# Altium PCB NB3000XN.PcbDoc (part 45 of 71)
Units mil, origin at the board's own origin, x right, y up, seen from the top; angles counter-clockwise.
Board outline 9527.56 x 6929.77 mil, 6 copper layers (Top Layer, GND+SHIELD, MidLayer1, MidLayer2, P2 - 3V3+5V0, Bottom Layer), stack 62.375 mil thick; 832 components, 1027 nets, 4655 pads, 4981 vias.
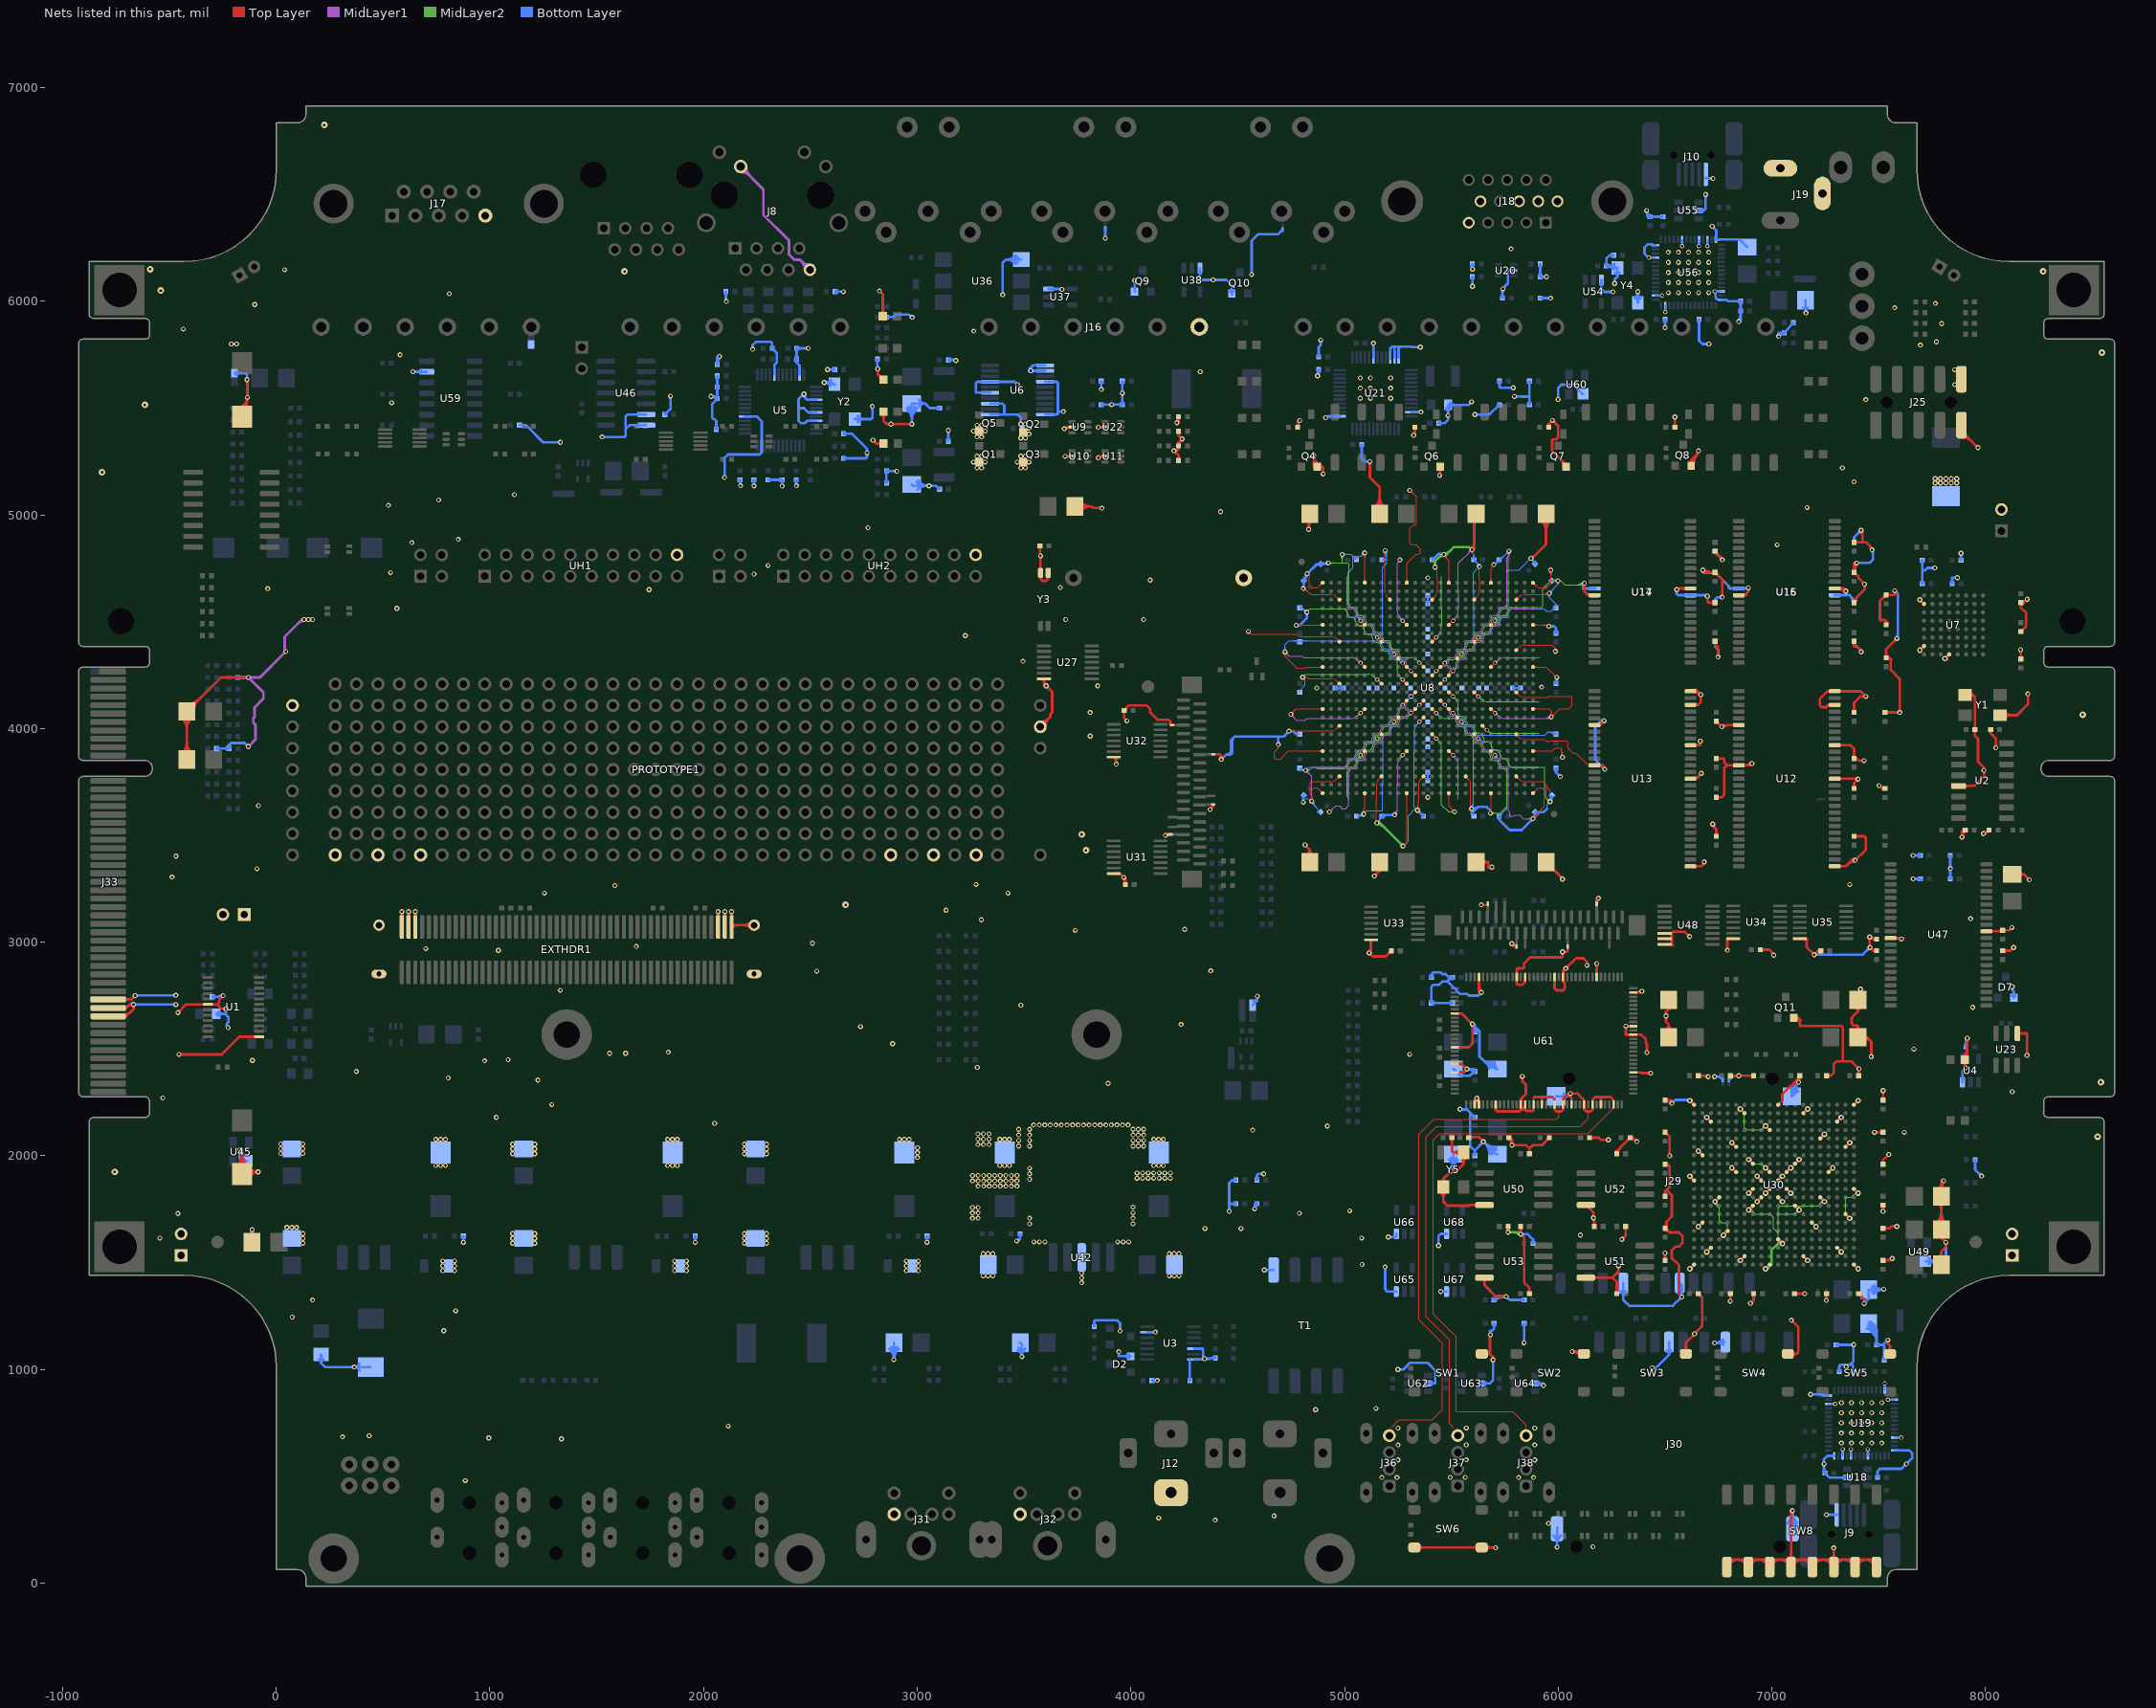
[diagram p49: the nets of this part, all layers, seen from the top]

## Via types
v1: diameter 23, hole 11.81, Top Layer to Bottom Layer, 3672 vias
v2: diameter 26, hole 11.81, Top Layer to Bottom Layer, 461 vias
v3: diameter 19, hole 11.81, Top Layer to Bottom Layer, tented both sides, 396 vias
v4: diameter 23.62, hole 11.81, Top Layer to Bottom Layer, 288 vias
v5: diameter 20, hole 11.81, Top Layer to Bottom Layer, 91 vias
v6: diameter 23, hole 11.81, Top Layer to Bottom Layer, tented both sides, 50 vias
v7: diameter 31, hole 11.81, Top Layer to Bottom Layer, 15 vias
v8: diameter 27.56, hole 11.81, Top Layer to Bottom Layer, tented both sides, 4 vias
v9: diameter 29, hole 11.81, Top Layer to Bottom Layer, 3 vias
v10: diameter 21, hole 11.81, Top Layer to Bottom Layer, 1 vias

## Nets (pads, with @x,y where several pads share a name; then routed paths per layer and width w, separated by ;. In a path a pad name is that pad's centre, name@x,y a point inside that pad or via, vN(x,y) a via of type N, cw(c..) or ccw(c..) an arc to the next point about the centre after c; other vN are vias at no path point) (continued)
GND: (continued)
  Bottom Layer w12: J33.B38@-785.98,2731.6 -678.25,2731.6 v1(-659.81,2750.04) -658.04,2751.81 v1(-470,2751.81) ; J33.B38@-711.58,2726.1 cw(c-698.3,2712.82) -698.3,2731.6 cw(c-698.3,2750.38) J33.B38@-711.58,2737.1 ; v1(-668.14,2708.37) -667.96,2708.19 v1(-470,2708.19) ; v1@-665.31,2750.04 cw(c-678.59,2750.04) -669.2,2740.65 cw(c-659.81,2731.26) v1@-659.81,2744.54 ; v1@-664.25,2704.49 cw(c-655.31,2695.55) -655.31,2708.19 ; v1@-664.25,2712.26 ccw(c-654.42,2722.1) -654.42,2708.19 ; v1@-655.92,2746.15 cw(c-642.26,2732.49) -642.26,2751.81 ; v1@-473.89,2704.3 ccw(c-483.28,2694.91) -483.28,2708.19 ccw(c-483.28,2721.47) v1@-473.89,2712.08 ; v1@-473.89,2747.92 ccw(c-483.28,2738.53) -483.28,2751.81 ccw(c-483.28,2765.09) v1@-473.89,2755.7 ; C21.2@-299.33,2745 -263.81,2745 -259.81,2749 -258.81,2750.04 v1(-248.48,2750.04) ; C21.2@-295.22,2740.89 cw(c-285.3,2730.97) -285.3,2745 ; C21.2@-295.22,2749.11 ccw(c-285.3,2759.03) -285.3,2745 ; C20.2@-280.63,2665 -239.81,2665 ; C13.2@-279.33,3906.82 C7.2@-220.67,3906.82 -220.67,3924.33 -212.63,3932.37 ; C13.2@-275.22,3902.71 cw(c-265.3,3892.79) -265.3,3906.82 ; C13.2@-275.22,3910.93 ccw(c-265.3,3920.85) -265.3,3906.82 ; -273.92,2745 ccw(c-273.92,2775.49) v1@-252.36,2753.93 ; C20.2@-270.95,2655.32 cw(c-247.59,2631.96) -247.59,2665 cw(c-247.59,2698.04) C20.2@-270.95,2674.68 ; v1@-238.36,2684.49 cw(c-247.75,2675.1) -234.48,2675.1 cw(c-221.2,2675.1) v1@-230.59,2684.49 ; v1(-234.48,2688.37) -234.48,2670.33 -239.81,2665 ; C7.2@-226.03,3903.73 cw(c-213.41,3910.99) -223.71,3921.29 ; v1(-225,2600) -233,2608 -233,2616.59 ; C7.2@-224.78,3902.71 ccw(c-234.7,3892.79) -234.7,3906.82 ccw(c-234.7,3920.85) -224.78,3910.93 ccw(c-234.7,3920.85) -220.67,3920.85 ccw(c-206.64,3920.85) C7.2@-216.56,3910.93 ; v1@-223.88,2605.38 cw(c-221.55,2616.59) -233,2616.59 ; C7.2@-215.63,3909.71 cw(c-199.33,3919.08) -212.63,3932.37 ; NT1.2@-194.76,5662.8 -142.79,5662.79 -136.48,5656.48 v1(-136.48,5633.37) -134.81,5631.71 v1(-134.81,5550.04) ; NT1.2@-187.87,5655.9 cw(c-171.23,5639.26) -171.23,5662.79 cw(c-171.23,5686.33) NT1.2@-187.87,5669.69 ; C18.2@-179.33,4239.55 -130.65,4239.54 v1(-130.48,4239.37) ; C18.2@-175.22,4235.44 cw(c-165.3,4225.52) -165.3,4239.54 ; C18.2@-175.22,4243.65 ccw(c-165.3,4253.57) -165.3,4239.54 ; v1(-171.14,2028.04) -171.14,1986.14 -161.69,1976.69 U45.1@-135.93,1976.69 ; -144.16,4239.54 cw(c-144.16,4225.69) v1@-134.36,4235.49 ; -143.34,4239.54 ccw(c-143.34,4252.24) v1@-134.36,4243.26 ; v1@-140.36,5629.49 cw(c-153.78,5616.07) -134.81,5616.07 ; v1@-140.36,5637.26 ccw(c-149.75,5646.65) -136.48,5646.65 ccw(c-123.2,5646.65) v1@-132.59,5637.26 ; v1@-138.7,5553.93 ccw(c-148.09,5563.32) -134.81,5563.32 ccw(c-121.53,5563.32) v1@-130.92,5553.93 ; v1@-135.98,3915.37 ccw(c-149.25,3915.37) -139.86,3924.76 ccw(c-130.48,3934.15) v1@-130.48,3920.87 ; v1(-130.48,3915.37) -147.48,3932.37 -212.63,3932.37 ; R111.2@199.3,1046.74 cw(c191.56,1030) 210,1030 ; R111.2@210,1069.88 210,1030 ; R111.2@220.7,1046.74 ccw(c228.44,1030) 210,1030 ; v1@361.3,1007.82 ccw(c351.91,998.43) 351.91,1011.71 ccw(c351.91,1024.99) v1@361.3,1015.6 ; v1@369.08,1007.82 cw(c378.72,998.18) 378.72,1011.81 ; v1@369.08,1015.6 ccw(c378.22,1024.74) 378.22,1011.81 ; C87.2@390.77,995.28 ccw(c365.19,983.76) v1@365.19,1011.81 ; C87.2@390.77,1028.34 cw(c365.19,1039.86) v1@365.19,1011.81 ; C87.2@439.24,1011.81 v1@365.19,1011.81 ; v4(639.92,5670.08) U59.15@704.59,5670.08 ; v4@644.03,5665.97 cw(c653.95,5656.05) 653.95,5670.08 cw(c653.95,5684.11) v4@644.03,5674.19 ; U59.15@677.44,5664.58 ccw(c664.16,5651.3) 664.16,5670.08 ccw(c664.16,5688.86) U59.15@677.44,5675.58 ; v1@872.29,1599.08 ccw(c862.9,1608.47) 876.18,1608.47 ccw(c889.46,1608.47) v1@880.07,1599.08 ; R206.2@872.42,1620.75 cw(c863.34,1611.67) 876.18,1611.67 cw(c889.02,1611.67) R206.2@879.94,1620.75 ; v1(876.18,1595.19) R206.2@876.18,1625 ; C151.2@1137.78,5420.08 1169.92,5420.08 1250,5340 v1(1330,5340) ; v1@1326.11,5336.11 ccw(c1316.72,5326.72) 1316.72,5340 ccw(c1316.72,5353.28) v1@1326.11,5343.89 ; v1(1525,5365) 1630,5365 1635,5370 1635,5401.16 ; v1@1528.89,5361.11 cw(c1538.28,5351.72) 1538.28,5365 cw(c1538.28,5378.28) v1@1528.89,5368.89 ; U46.7@1695.94,5415.97 ccw(c1686.02,5406.05) 1686.02,5420.08 ccw(c1686.02,5434.11) U46.7@1695.94,5424.19 ; U46.6@1695.94,5465.97 ccw(c1686.02,5456.05) 1686.02,5470.08 ccw(c1686.02,5484.11) U46.6@1695.94,5474.19 ; U46.7@1731.54,5420.08 1653.92,5420.08 1635,5401.16 ; U46.6@1731.54,5470.08 1645.08,5470.08 1635,5460 1635,5401.16 ; C152.1@1819.33,5470 1845.19,5495.86 v1(1845.19,5556.71) ; C152.1@1819.33,5475.81 ccw(c1819.33,5489.84) 1829.25,5479.92 ccw(c1839.17,5470) C152.1@1825.14,5470 ; v1@1841.3,5552.82 cw(c1831.91,5543.43) 1845.19,5543.43 cw(c1858.47,5543.43) v1@1849.08,5552.82 ; v1@1957.29,1598.89 ccw(c1947.9,1608.28) 1961.18,1608.28 ccw(c1974.46,1608.28) v1@1965.07,1598.89 ; R204.2@1957.42,1620.75 cw(c1948.34,1611.67) 1961.18,1611.67 cw(c1974.02,1611.67) R204.2@1964.94,1620.75 ; v1(1961.18,1595) R204.2@1961.18,1625 ; v1@2038.89,5551.11 cw(c2048.28,5541.72) 2048.28,5555 cw(c2048.28,5568.28) v1@2038.89,5558.89 ; 2052.94,5531.08 ccw(c2039.51,5544.51) R52.2@2058.5,5544.51 ; C50.1@2055.22,5404.11 ccw(c2045.3,5414.03) 2059.33,5414.03 ccw(c2073.36,5414.03) C50.1@2063.44,5404.11 ; C50.1@2059.33,5400 2059.33,5440.37 2052,5447.71 2048.52,5447.71 2040.19,5456.04 2040.19,5518.33 2063.82,5541.96 R52.2@2063.82,5545 ; R52.2@2059.49,5542.4 ccw(c2035,5524.9) v1(2035,5555) 2053.82,5555 R52.2@2063.82,5545 ; R52.2@2060.06,5549.25 ccw(c2050.98,5558.33) 2063.82,5558.33 ccw(c2076.66,5558.33) R52.2@2067.58,5549.25 ; R51.2@2060.06,5594.08 cw(c2050.98,5585) 2063.82,5585 ; R51.2@2060.06,5602.59 ccw(c2050.98,5611.67) 2063.82,5611.67 ccw(c2076.66,5611.67) R51.2@2067.58,5602.59 ; R47.2@2060.06,5647.41 cw(c2050.98,5638.33) 2063.82,5638.33 cw(c2076.66,5638.33) R47.2@2067.58,5647.41 ; R46.2@2060.06,5709.25 ccw(c2050.98,5718.33) 2063.82,5718.33 ccw(c2076.66,5718.33) R46.2@2067.58,5709.25 ; 2063.82,5585 cw(c2076.66,5585) R51.2@2067.58,5594.08 ; R47.2@2063.82,5651.67 R51.2@2063.82,5598.33 R52.2@2063.82,5545 ; R46.2@2063.82,5703.47 cw(c2111.53,5703.47) v1@2078.35,5737.76 ; R46.2@2063.82,5705 2063.82,5731.04 2066.15,5733.37 ; 2063.82,5731.79 cw(c2084.13,5731.79) v1@2070,5746.38 ; v1(2074.52,5741.71) 2066.15,5733.37 ; v1(2074.52,5741.71) 2066.19,5733.37 ; v1@2094.64,5179.08 ccw(c2085.25,5188.47) 2098.52,5188.47 ccw(c2111.8,5188.47) v1@2102.41,5179.08 ; v1(2098.52,5175.19) 2098.52,5266.37 2115.19,5283.04 2263.62,5283.04 2272.28,5291.71 U5.11@2272.28,5322.68 2272.28,5437.72 2252.85,5457.15 ; C43.2@2100.22,6040.89 cw(c2090.3,6030.97) 2104.33,6030.97 cw(c2118.36,6030.97) C43.2@2108.44,6040.89 ; 2104.33,6018.42 ccw(c2126.23,6018.42) v1@2110.75,6002.93 ; C43.2@2104.33,6045 2104.33,6001.57 v1(2106.86,5999.04) ; R45.2@2166.24,5160.06 cw(c2157.16,5150.98) 2170,5150.98 cw(c2182.84,5150.98) R45.2@2173.76,5160.06 ; R45.2@2170,5157.69 ccw(c2194.17,5157.69) v1@2177.08,5140.6 ; R45.2@2170,5163.82 2170,5139.71 2170.19,5139.71 v1(2173.19,5136.71) ; U5.17@2193.54,5460.47 2249.53,5460.47 2252.85,5457.15 ; v1@2226.11,5778.89 ccw(c2216.72,5788.28) 2230,5788.28 ccw(c2243.28,5788.28) v1@2233.89,5778.89 ; v1(2230,5775) 2230,5795 2245,5810 2315,5810 2321.18,5803.82 R56.1@2321.18,5780 2342.5,5758.68 2342.5,5712.35 2331.34,5701.19 U5.29@2331.34,5657.32 ; v1@2231.97,5140.26 ccw(c2222.23,5150) 2236,5150 ; R44.2@2232.24,5160.06 cw(c2223.16,5150.98) 2236,5150.98 cw(c2248.84,5150.98) R44.2@2239.76,5160.06 ; v1@2235.71,5136.52 2235.86,5136.52 v1@2236,5136.52 ; 2236,5149.31 ccw(c2248.79,5149.31) v1@2239.75,5140.26 ; R44.2@2236,5163.82 v1@2236,5136.52 ; v1@2236.67,5135.56 v1(2235.86,5136.37) v1@2236,5136.52 ; 2255,5455 2252.85,5457.15 ; 2267.34,5286.76 ccw(c2255.38,5298.72) U5.11@2272.28,5299.15 ; R43.2@2302,5163.82 R42.2@2368,5163.82 v1(2368,5135) ; R43.2@2306.25,5160.06 cw(c2315.33,5150.98) 2315.33,5163.82 cw(c2315.33,5176.66) R43.2@2306.25,5167.58 ; R56.1@2317.42,5784.25 ccw(c2308.34,5793.33) 2321.18,5793.33 ccw(c2334.02,5793.33) R56.1@2324.94,5784.25 ; R56.1@2321.18,5774.19 cw(c2321.18,5760.16) R56.1@2331.1,5770.08 ; R56.1@2326.5,5779.51 ccw(c2338.15,5779.51) R56.1@2329.91,5771.27 ; R42.2@2363.75,5160.06 ccw(c2354.67,5150.98) 2354.67,5163.82 ccw(c2354.67,5176.66) R42.2@2363.75,5167.58 ; v1@2364.11,5138.89 ccw(c2354.72,5148.28) 2368,5148.28 ccw(c2381.28,5148.28) v1@2371.89,5138.89 ; R42.2@2364.24,5160.06 cw(c2355.16,5150.98) 2368,5150.98 cw(c2380.84,5150.98) R42.2@2371.76,5160.06 ; R41.2@2430.24,5160.06 cw(c2421.16,5150.98) 2434,5150.98 cw(c2446.84,5150.98) R41.2@2437.76,5160.06 ; R41.2@2430.73,5160.06 cw(c2420.42,5149.75) 2435,5149.75 ; C44.2@2430.8,5733.82 ccw(c2440.39,5726.3) 2431.77,5717.68 ; v1@2431.3,5140.6 ccw(c2422.37,5149.53) 2435,5149.53 ; C44.2@2431.56,5734.11 ccw(c2421.64,5744.03) 2435.67,5744.03 ccw(c2449.7,5744.03) C44.2@2439.78,5734.11 ; C47.1@2431.56,5775.89 cw(c2421.64,5765.97) 2435.67,5765.97 cw(c2449.7,5765.97) 2439.78,5775.89 cw(c2449.7,5765.97) 2449.7,5780 ; R41.2@2434,5152.86 ccw(c2451.34,5152.86) 2439.08,5140.6 cw(c2448.93,5150.44) 2435,5150.44 ; 2435,5152.2 cw(c2446.11,5152.2) R41.2@2438.25,5160.06 ; C47.1@2439.78,5784.11 ccw(c2449.7,5794.03) 2449.7,5780 ; C44.2@2440.24,5726.41 ccw(c2451.11,5717.88) 2441.34,5708.11 ; 2445,5485 2445,5455 ; U5.35@2449.45,5657.32 2449.45,5700 2435.67,5713.78 C44.2@2435.67,5730 C47.1@2435.67,5775.04 ; v4@2464.19,5566.71 cw(c2450.16,5566.71) 2460.08,5556.79 cw(c2470,5546.87) v4@2470,5560.9 ; v4@2475.21,5564.14 ccw(c2489.68,5557.02) 2478.28,5545.62 ; v1@2484.23,5780 C47.1@2440.63,5780 ; v1@2486.11,5776.11 ccw(c2476.72,5766.72) 2476.72,5780 ccw(c2476.72,5793.28) v1@2486.11,5783.89 ; U5.45@2528.19,5440.79 2485.79,5440.79 2475,5430 2455,5430 2445,5440 2445,5455 ; U5.43@2528.19,5480.16 2489.84,5480.16 2470,5500 2445,5500 ; U5.40@2528.19,5539.21 2484.68,5539.21 2470,5553.9 v4(2470,5566.71) 2445,5541.71 2445,5500 ; v4@2569.11,5615.89 cw(c2579.03,5605.97) 2579.03,5620 cw(c2579.03,5634.03) v4@2569.11,5624.11 ; v4@2571.46,5620 ccw(c2571.46,5656.54) Y2.4@2597.3,5630.7 ; v4(2580,5680) C45.1@2614.33,5680 C45.1@2612.5,5680 ; v4@2584.11,5675.89 cw(c2594.03,5665.97) 2594.03,5680 cw(c2594.03,5694.03) v4@2584.11,5684.11 ; Y2.4@2594.39,5603.91 ccw(c2565,5585.11) v4(2565,5620) 2596.5,5620 2605,5611.5 Y2.4@2612.5,5611.5 ; C45.1@2610.22,5675.89 ccw(c2600.3,5665.97) 2600.3,5680 ccw(c2600.3,5694.03) C45.1@2610.22,5684.11 ; C48.1@2615.67,6045 v1(2655,6045) ; C48.1@2619.78,6040.89 cw(c2629.7,6030.97) 2629.7,6045 cw(c2629.7,6059.03) C48.1@2619.78,6049.11 ; C51.1@2655.67,5265 2760,5265 2765,5270 v1(2765,5290) 2765,5310 2695,5380 C46.1@2655.67,5380 ; C51.1@2659.78,5260.89 cw(c2669.7,5250.97) 2669.7,5265 cw(c2669.7,5279.03) C51.1@2659.78,5269.11 ; C46.1@2659.78,5375.89 cw(c2669.7,5365.97) 2669.7,5380 cw(c2669.7,5394.03) C46.1@2659.78,5384.11 ; Y2.2@2707.5,5448.5 2783.5,5448.5 2790.19,5455.19 v1(2790.19,5508.37) ; Y2.2@2722.7,5433.3 cw(c2759.41,5396.59) 2759.41,5448.5 cw(c2759.41,5500.41) Y2.2@2722.7,5463.7 ; v1@2761.11,5286.11 cw(c2751.72,5276.72) 2765,5276.72 cw(c2778.28,5276.72) v1@2768.89,5286.11 ; v1@2761.11,5293.89 ccw(c2751.72,5303.28) 2765,5303.28 ccw(c2778.28,5303.28) v1@2768.89,5293.89 ; v1@2786.3,5504.49 cw(c2776.91,5495.1) 2790.19,5495.1 cw(c2803.47,5495.1) v1@2794.08,5504.49 ; R64.1@2810.06,5725.75 cw(c2800.98,5716.67) 2813.82,5716.67 cw(c2826.66,5716.67) R64.1@2817.58,5725.75 ; 2813.82,5699.96 ccw(c2831.78,5699.96) v1@2819.08,5687.26 ; R64.1@2813.82,5730 2813.82,5684.75 v1(2815.19,5683.37) ; R61.2@2852.42,5154.25 ccw(c2843.34,5163.33) 2856.18,5163.33 ccw(c2869.02,5163.33) R61.2@2859.94,5154.25 ; R65.2@2852.42,5200.75 cw(c2843.34,5191.67) 2856.18,5191.67 cw(c2869.02,5191.67) R65.2@2859.94,5200.75 ; R61.2@2856.18,5150 R65.2@2856.18,5205 2904.23,5205 v1(2904.52,5204.71) ; R60.1@2856.18,5926 2887.63,5926 2900,5938.37 2915.19,5938.37 2960.19,5938.37 2973.52,5925.04 v1(2976.52,5925.04) ; R65.2@2859.94,5201.24 cw(c2869.02,5192.16) 2869.02,5205 cw(c2869.02,5217.84) R65.2@2859.94,5208.76 ; R60.1@2859.94,5922.24 cw(c2869.02,5913.16) 2869.02,5926 cw(c2869.02,5938.84) R60.1@2859.94,5929.76 ; C62.2@2869.74,1096.21 cw(c2825.12,1046.38) v1@2892.01,1046.38 ; C62.2@2877.75,1105.14 cw(c2849.17,1073.24) 2892.01,1073.24 cw(c2934.84,1073.24) C62.2@2906.27,1105.14 ; v1@2886.3,1050.26 ccw(c2872.52,1064.04) 2892.01,1064.04 ; v1(2890.19,1046.37) 2892.01,1044.56 v1@2892.01,1046.37 ; 2890.54,5205 cw(c2890.54,5190.72) v1@2900.64,5200.82 ; 2891.95,5205 ccw(c2891.95,5217.28) v1@2900.64,5208.6 ; C62.2@2892.01,1125 v1@2892.01,1046.37 ; C62.2@2914.27,1096.21 ccw(c2958.9,1046.38) v1@2892.01,1046.38 ; C49.2@2951.4,5498.41 cw(c2894.44,5441.45) 2975,5441.45 cw(c3055.56,5441.45) C49.2@2998.6,5498.41 ; C49.2@2959.89,5506.9 cw(c2923.41,5470.42) 2975,5470.42 cw(c3026.59,5470.42) C49.2@2990.11,5506.9 ; 2962.01,5936.55 ccw(c2976.52,5951.06) v1@2976.52,5930.54 ; v1@2971.11,5428.89 ccw(c2961.72,5438.28) 2975,5438.28 ccw(c2988.28,5438.28) v1@2978.89,5428.89 ; C40.2@2975,5142.01 2980.63,5136.37 v1(3055.19,5136.37) ; v1(2975,5425) C49.2@2975,5522.01 3037.22,5522.01 ; C40.2@2996.27,5154.51 ccw(c3031.73,5180.11) 3031.73,5136.37 ; C40.2@3002.53,5118.41 cw(c3045.9,5075.04) v1@3045.9,5136.37 ; C40.2@3006,5161.54 ccw(c3055.19,5197.04) v1(3055.19,5136.37) ; C49.2@3007.71,5505.11 cw(c3037.22,5487.79) 3037.22,5522.01 ; C49.2@3007.71,5538.9 ccw(c3037.22,5556.22) 3037.22,5522.01 ; v1@3042.29,1598.89 ccw(c3032.9,1608.28) 3046.18,1608.28 ccw(c3059.46,1608.28) v1@3050.07,1598.89 ; R202.2@3042.42,1620.75 cw(c3033.34,1611.67) 3046.18,1611.67 cw(c3059.02,1611.67) R202.2@3049.94,1620.75 ; v1(3046.18,1595) R202.2@3046.18,1625 ; v1@3051.3,5132.49 ccw(c3041.91,5123.1) 3041.91,5136.37 ccw(c3041.91,5149.65) v1@3051.3,5140.26 ; v1@3059.08,5132.49 cw(c3068.47,5123.1) 3068.47,5136.37 cw(c3068.47,5149.65) v1@3059.08,5140.26 ; C42.1@3098.52,5120 ccw(c3084.49,5120) 3094.41,5129.92 ccw(c3104.33,5139.84) C42.1@3104.33,5125.81 ; C53.1@3100.22,5495.89 ccw(c3090.3,5485.97) 3090.3,5500 ccw(c3090.3,5514.03) C53.1@3100.22,5504.11 ; C42.1@3104.33,5120 3087.96,5136.37 v1(3055.19,5136.37) ; C53.1@3104.33,5500 3059.23,5500 3037.22,5522.01 ; C41.1@3145.67,5345 v1(3145.67,5395.67) ; C52.1@3145.67,5725 3147.09,5726.42 3177.58,5726.42 v1(3181,5723) ; C52.1@3149.78,5720.89 cw(c3163.13,5707.53) 3163.13,5726.42 ; 3159.46,5726.42 cw(c3159.46,5701.46) v1@3177.11,5719.11 ; U6.11@3341.06,5469.84 3407.86,5469.84 ; U6.13@3341.06,5521.02 3398.52,5521.02 3407.86,5511.69 3407.86,5469.84 ; U6.15@3341.06,5572.2 3275,5572.2 3275,5617.86 3280.52,5623.39 U6.17@3341.06,5623.39 3456.61,5623.39 v1(3470,5610) ; v1@3396.11,6033.89 ccw(c3386.72,6043.28) 3400,6043.28 ccw(c3413.28,6043.28) v1@3403.89,6033.89 ; v1(3400,6030) 3400,6180 3415,6195 ; U36.4@3461.44,6175.04 ccw(c3415,6131) 3415,6195 ; U36.4@3461.44,6214.96 cw(c3415,6259) 3415,6195 ; v1(3465.19,1602.04) 3472.04,1602.04 3481.18,1611.18 ; v1@3466.65,1607.34 ccw(c3470.62,1621.74) 3481.18,1611.18 ; C61.2@3469.39,1090.17 cw(c3456.85,1059.48) v1@3490,1059.48 ; U36.4@3470.15,6183.3 ccw(c3442.92,6157.48) 3442.92,6195 ccw(c3442.92,6232.52) U36.4@3470.15,6206.7 ; C61.2@3473.93,1101.28 cw(c3464.15,1077.35) 3490,1077.35 ; R208.2@3477.42,1630.75 cw(c3468.34,1621.67) 3481.18,1621.67 cw(c3494.02,1621.67) R208.2@3484.94,1630.75 ; v1@3481.11,5429.09 ccw(c3471.72,5438.47) 3485,5438.47 ccw(c3498.28,5438.47) v1@3488.89,5429.09 ; R208.2@3481.18,1635 3481.18,1611.18 ; C61.2@3482.01,1125 3490,1117.01 v1(3490,1060) ; v1(3485,5425.2) 3485,5455 3470.16,5469.84 3407.86,5469.84 ; v1@3486.11,1063.89 ccw(c3476.72,1073.28) 3490,1073.28 ccw(c3503.28,1073.28) v1@3493.89,1063.89 ; U36.4@3487.48,6195 3415,6195 ; v1@3490,1059.8 cw(c3543.28,1059.8) C61.2@3505.6,1097.47 ; v1@3526.02,5671.7 cw(c3539,5678.07) 3528.78,5688.29 ; v1@3527.97,5678.46 ccw(c3518.58,5687.84) 3531.86,5687.84 ccw(c3545.14,5687.84) 3535.75,5678.46 ccw(c3545.14,5687.84) 3545.14,5674.57 ccw(c3545.14,5661.29) v1@3535.75,5670.68 ; v1@3536.79,5676.99 cw(c3554.91,5685.89) 3540.64,5700.16 ; U6.10@3598.94,5469.84 3653.52,5469.84 3658.52,5474.84 3658.52,5483.37 ; U6.4@3598.94,5623.39 3653.52,5623.39 3658.52,5618.39 3658.52,5483.37 ; U6.2@3598.94,5674.57 v1(3531.86,5674.57) 3531.86,5691.37 3540.64,5700.16 ; U6.1@3598.94,5700.16 3540.64,5700.16 ; U37.3@3614.88,6057.4 3675.83,6057.4 v1(3677.52,6055.71) v1@3680,6058.18 ; U37.3@3632.77,6053.29 cw(c3642.69,6043.37) 3642.69,6057.4 cw(c3642.69,6071.43) U37.3@3632.77,6061.51 ; 3660.16,6057.4 cw(c3660.16,6038.34) v1@3673.64,6051.82 ; 3671.25,5483.37 ccw(c3671.25,5497.32) v1@3681.11,5487.46 ; 3672.19,5483.37 cw(c3672.19,5470.76) v1@3681.11,5479.68 ; v1@3681.86,5483.37 3658.52,5483.37 ; R36.2@3829,1201.18 3829,1227.04 3831.96,1230 3937.04,1230 3950,1217.04 v1(3950,1180) ; C243.2@3857.62,5622.07 cw(c3847.7,5612.15) 3861.73,5612.15 cw(c3875.75,5612.15) C243.2@3865.83,5622.07 ; v1@3857.97,5590.79 ccw(c3848.9,5599.86) 3861.73,5599.86 ; C244.2@3861.72,5516.18 3910,5516.18 C259.2@3960.39,5516.18 v1(3960.39,5570.19) C229.2@3960.39,5626.18 ; 3861.73,5600.5 ccw(c3875.45,5600.5) v1@3865.75,5590.79 ; C243.2@3861.72,5626.18 3861.73,5586.9 3861.73,5586.71 v1@3861.86,5586.71 ; C244.2@3865.83,5512.07 cw(c3875.75,5502.15) 3875.75,5516.18 cw(c3875.75,5530.21) C244.2@3865.83,5520.29 ; v1@3880,6293.14 NT47.1@3880,6340 ; 3896.25,5516.18 ccw(c3896.25,5530.12) v1@3906.11,5520.26 ; 3897.19,5516.18 cw(c3897.19,5503.56) v1@3906.11,5512.48 ; v1@3913.89,5512.48 cw(c3922.81,5503.56) 3922.81,5516.18 ; v1@3913.89,5520.26 ccw(c3923.75,5530.12) 3923.75,5516.18 ; v1(3943.52,1083.37) 3943.52,1062.71 3943.22,1062.4 D2.1@3999.21,1062.4 ; C259.2@3956.28,5512.07 ccw(c3946.36,5502.15) 3946.36,5516.18 ccw(c3946.36,5530.21) 3956.28,5520.29 ccw(c3946.36,5530.21) 3960.39,5530.21 ccw(c3974.42,5530.21) C259.2@3964.5,5520.29 ; C229.2@3956.28,5622.07 cw(c3946.36,5612.15) 3960.39,5612.15 cw(c3974.42,5612.15) C229.2@3964.5,5622.07 ; v1@3956.5,5566.3 cw(c3947.11,5556.92) 3960.39,5556.92 cw(c3973.66,5556.92) v1@3964.28,5566.3 ; v1@3956.5,5574.08 ccw(c3947.11,5583.47) 3960.39,5583.47 ccw(c3973.66,5583.47) v1@3964.28,5574.08 ; D2.1@3989.94,1054.12 ccw(c3969.94,1034.11) 3969.94,1062.4 ccw(c3969.94,1090.69) D2.1@3989.94,1070.69 ; v1@4013.71,6093.71 cw(c4004.32,6084.32) 4017.6,6084.32 cw(c4030.88,6084.32) v1@4021.49,6093.71 ; Q9.3@4017.6,6045.79 v1(4017.6,6097.6) ; U3.13@4076.5,1174.41 4090.19,1174.41 4090.19,1175.04 v1@4112.52,1175.04 ; C37.1@4098.67,949 v1(4124,949) ; C37.1@4102.78,944.89 cw(c4112.7,934.97) 4112.7,949 cw(c4112.7,963.03) C37.1@4102.78,953.11 ; v1@4120.11,945.11 ccw(c4110.72,935.72) 4110.72,949 ccw(c4110.72,962.28) v1@4120.11,952.89 ; R34.2@4272.4,953.25 ccw(c4263.32,962.33) 4276.16,962.33 ccw(c4289,962.33) R34.2@4279.92,953.25 ; R34.2@4276.16,949 U3.7@4276.16,1043.84 ; U3.7@4295,1046.46 4336.86,1046.46 4338.52,1048.12 v1@4338.52,1050.04 ; U3.5@4295,1097.64 4336.86,1097.64 4338.52,1095.97 v1@4338.52,1050.04 ; U38.3@4323.24,6155.12 4323.24,6125.04 4323.52,6124.76 4323.52,6103.71 4327.19,6100.04 4446.52,6100.04 4472.6,6073.97 Q10.3@4472.6,6035.79 4472.6,6033.37 Q10.3@4473.52,6033.37 ; R38.1@4390.75,1050.06 ccw(c4381.67,1040.98) 4381.67,1053.82 ccw(c4381.67,1066.66) R38.1@4390.75,1057.58 ; R38.1@4395,1053.82 4374.19,1053.82 4370.52,1050.15 4370.52,1050.04 v1(4345,1050.04) v1@4338.52,1050.04 ; v1(4423.52,3855.71) 4446.86,3879.04 4455,3879.04 ; v1@4423.52,3861.21 ccw(c4423.52,3874.49) 4432.91,3865.1 ccw(c4442.3,3855.71) v1@4429.02,3855.71 ; v1@4456.11,1743.89 ccw(c4446.72,1753.28) 4460,1753.28 ccw(c4473.28,1753.28) v1@4463.89,1743.89 ; v1(4460,1740) 4460,1775 ; Q10.3@4464.31,6045.06 ccw(c4444.31,6065.06) 4472.6,6065.06 ccw(c4500.88,6065.06) Q10.3@4480.88,6045.06 ; C216.2@4487.62,1772.07 ccw(c4477.7,1762.15) 4477.7,1776.18 ccw(c4477.7,1790.21) C216.2@4487.62,1780.29 ; C232.2@4487.62,1882.07 ccw(c4477.7,1872.15) 4477.7,1886.18 ccw(c4477.7,1900.21) C232.2@4487.62,1890.29 ; C216.2@4491.72,1776.18 4461.18,1776.18 4460,1775 ; C232.2@4491.72,1886.18 4473.52,1886.18 4460,1872.65 4460,1775 ; v1@4561.3,6129.12 ccw(c4551.91,6138.51) 4565.19,6138.51 ccw(c4578.47,6138.51) v1@4569.08,6129.12 ; v1@4565.19,6125.04 v1(4565.19,6125.23) 4565.19,6283.37 4595.19,6313.37 4688.37,6313.37 NT48.1@4710,6335 ; NT44.1@4569.76,2705.08 4592,2727.31 ; NT44.1@4573.91,2724.15 ccw(c4580.7,2738.61) 4592,2727.31 ; v1@4579.6,1749.73 cw(c4603.15,1749.73) C252.2@4592.91,1770.94 ; C252.2@4579.6,1768.85 cw(c4593.92,1768.85) C252.2@4587.7,1781.75 ; v1@4580,1752.4 v1(4579.6,1752.03) 4579.6,1765.39 C252.2@4590.39,1776.18 ccw(c4606.21,1760.35) v1@4584.85,1753.67 ; C251.2@4586.28,1890.29 ccw(c4576.36,1900.21) 4590.39,1900.21 ccw(c4604.42,1900.21) C251.2@4594.5,1890.29 ; v1@4588.11,2744.11 cw(c4578.72,2734.72) 4592,2734.72 cw(c4605.28,2734.72) v1@4595.89,2744.11 ; C251.2@4590.39,1886.18 4590.39,1910 4596.39,1916 v1(4622,1916) ; v1(4592,2748) 4592,2727.31 ; v1@4618.11,1912.11 ccw(c4608.72,1902.72) 4608.72,1916 ccw(c4608.72,1929.28) v1@4618.11,1919.89 ; v1(4625,1466) T1.1@4668,1466 ; v1@4686.3,3928.93 ccw(c4676.91,3938.32) 4690.19,3938.32 ccw(c4703.47,3938.32) v1@4694.08,3928.93 ; v1(4690.19,3925.04) 4690.19,3962.04 ; 4702.32,6327.32 cw(c4710,6319.64) NT48.1@4710,6330.5 ; v1@4734.69,3987.71 cw(c4721.41,3987.71) 4730.8,3978.32 cw(c4740.19,3968.93) v1@4740.19,3982.21 ; v1@4744.08,3983.82 cw(c4753.47,3974.43) 4753.47,3987.71 cw(c4753.47,4000.99) v1@4744.08,3991.6 ; 4765.19,3982.78 4773.52,3974.45 ; 4765.19,3983.04 4760.52,3987.71 v1(4740.19,3987.71) 4714.52,3962.04 4690.19,3962.04 ; v1(4773.52,4483.37) 4790.19,4483.37 ; v1@4777.41,4479.49 cw(c4786.8,4470.1) 4786.8,4483.37 cw(c4786.8,4496.65) v1@4777.41,4487.26 ; C310.2@4806.36,4696.51 ccw(c4792.44,4717.37) 4817.52,4717.37 4817.52,4699.61 C310.2@4809.59,4691.67 ; 4806.86,4500.04 4790.19,4483.37 ; 4806.92,3669.37 v1(4806.86,3655.37) 4806.86,3685.6 C327.2@4809.59,3688.33 ; v1@4809.59,4659.98 v1@4809.86,4659.71 ; C310.2@4817.52,4698.48 cw(c4845.4,4698.48) v1@4828.52,4720.66 ; v1@4819.64,4540.82 cw(c4810.25,4531.43) 4823.52,4531.43 cw(c4836.8,4531.43) v1@4827.41,4540.82 ; v1(4823.52,4544.71) 4823.52,4516.71 4790.19,4483.37 ; v1(4825.19,4725.04) 4866.86,4766.71 ; v1@4825.19,4730.54 ccw(c4825.19,4743.82) 4834.58,4734.43 ccw(c4843.97,4725.04) v1@4830.69,4725.04 ; 4867,4768 4888.3,4770.61 v1@4917.69,4774.2 ; v1@4869.64,5655.26 ccw(c4846.23,5678.67) C100.2@4879.33,5678.67 ; v1(4873.52,5651.37) 4874.52,5650.37 4875.33,5650.37 4879.33,5654.37 C100.2@4879.33,5680 ; C294.2@4873.91,4768.85 cw(c4875.69,4754.25) C294.2@4884.75,4765.83 ; C294.2@4874.85,4768.96 ccw(c4873.23,4782.22) C294.2@4883.75,4773.99 ; R116.1@4875.06,5744.25 ccw(c4865.98,5753.33) 4878.82,5753.33 ccw(c4891.66,5753.33) R116.1@4882.58,5744.25 ; C100.2@4875.22,5675.89 cw(c4865.3,5665.97) 4879.33,5665.97 cw(c4893.36,5665.97) C100.2@4883.44,5675.89 ; R116.1@4879.33,5739.49 R116.1@4878.82,5740 4878.82,5785 4888.52,5794.7 v1(4888.52,5818.37) ; v1@4884.64,5814.49 cw(c4875.25,5805.1) 4888.52,5805.1 cw(c4901.8,5805.1) v1@4892.41,5814.49 ; C294.2@4888.33,4770.41 4913.89,4770.41 v1@4917.69,4774.2 ; C294.2@4891.91,4774.99 ccw(c4900.13,4785.51) C294.2@4901.76,4772.25 ; C294.2@4892.44,4766.3 cw(c4902.36,4756.38) 4902.36,4770.41 cw(c4902.36,4784.44) C294.2@4892.44,4774.52 ; C294.2@4892.91,4766.83 cw(c4904.49,4757.78) C294.2@4902.7,4772.37 ; C294.2@4900.07,4770.41 ccw(c4900.07,4799.49) v1@4920.64,4778.93 ; v1(4910.86,5455.37) 4915.86,5460.37 4923.14,5460.37 4924.5,5461.73 U21.25@4977.68,5461.73 ; v1@4914.75,5451.49 cw(c4939.48,5426.75) 4939.48,5461.73 ; v1@4920.19,4778.43 cw(c4909.73,4786.61) 4911.34,4773.43 cw(c4912.96,4760.25) v1@4921.14,4770.71 ; C318.2@4956.93,4190 C302.2@4994.33,4190 ; C318.2@4961.04,4185.89 cw(c4970.96,4175.97) 4970.96,4190 cw(c4970.96,4204.03) C318.2@4961.04,4194.11 ; C302.2@4990.22,4185.89 ccw(c4980.3,4175.97) 4980.3,4190 ccw(c4980.3,4204.03) C302.2@4990.22,4194.11 ; C96.2@5076.56,5325.89 cw(c5066.64,5315.97) 5080.67,5315.97 cw(c5094.7,5315.97) C96.2@5084.78,5325.89 ; C96.2@5080.67,5330 5080.67,5264.33 5094.96,5250.04 v1(5118.86,5250.04) ; v1@5114.97,5246.15 ccw(c5105.58,5236.76) 5105.58,5250.04 ccw(c5105.58,5263.32) v1@5114.97,5253.93 ; v1@5131.3,5800.15 cw(c5121.99,5790.84) 5135.16,5790.84 ; U21.42@5135.16,5737.32 v1@5135.16,5804.01 ; 5135.16,5790.69 cw(c5148.55,5790.69) v1@5139.08,5800.15 ; C330.2@5177.6,3594.88 ccw(c5182.35,3602.22) 5188.52,3596.04 ; C330.2@5178.56,3585.89 cw(c5203.06,3561.39) 5203.06,3596.04 ; C330.2@5180.17,3589.01 cw(c5188.52,3587.57) 5188.52,3596.04 ; C330.2@5181.86,3589.37 5188.52,3596.04 ; v1(5190,1480) 5190,1375 5200,1365 5242.48,1365 U65.3@5242.6,1364.88 ; v1(5205,1620) 5240,1620 5242.6,1622.6 5242.6,1633.19 U66.3@5242.6,1634.88 ; U21.46@5213.9,5731.74 U21.46@5213.9,5737.32 5213.9,5778.9 5223.21,5788.21 5235,5788.21 ; v1@5230.64,3592.15 ccw(c5221.25,3582.76) 5221.25,3596.04 ccw(c5221.25,3609.32) v1@5230.64,3599.93 ; U21.47@5233.58,5737.32 5233.58,5786.79 5235,5788.21 ; v1(5234.52,3596.04) 5188.52,3596.04 ; v4(5250,1000) 5275,1000 5306.54,1031.54 5388.46,1031.54 5425,995 5425,935 U62.2@5392.24,935 ; U21.48@5253.27,5737.32 5253.27,5778.27 5263.21,5788.21 ; v4@5254.11,995.89 cw(c5264.03,985.97) 5264.03,1000 cw(c5264.03,1014.03) v4@5254.11,1004.11 ; U21.11@5312.32,5481.42 v1(5357.86,5481.37) v1(5357.86,5481.37) ; v1@5341.52,3612.54 cw(c5341.52,3599.26) 5350.91,3608.65 cw(c5360.3,3618.04) v1@5347.02,3618.04 ; v1(5341.52,3618.04) C333.2@5365.19,3594.37 ; 5344.48,5481.42 cw(c5344.48,5468) v1@5353.97,5477.49 ; 5344.68,5481.42 ccw(c5344.68,5494.55) v1@5353.97,5485.26 ; v4@5350.89,5780.89 ccw(c5340.97,5770.97) 5340.97,5785 ccw(c5340.97,5799.03) v4@5350.89,5789.11 ; v4(5355,5785) 5315.64,5785 5312.43,5788.21 5263.21,5788.21 ; C333.2@5359.25,3600.32 cw(c5348.93,3590) C333.2@5363.52,3590 ; C333.2@5359.81,3599.75 ccw(c5369.33,3609.28) C333.2@5369.33,3595.81 ; C333.2@5365.19,3590 C333.2@5369.33,3590 ; C193.2@5401.24,2832.14 cw(c5412.36,2837.94) C193.2@5403.49,2846.8 ; C192.2@5402.62,2719.11 ccw(c5392.7,2729.03) 5406.73,2729.03 ccw(c5420.75,2729.03) 5410.83,2719.11 ccw(c5420.75,2729.03) 5420.75,2715 ccw(c5420.75,2700.97) C192.2@5410.83,2710.89 ; C193.2@5402.62,2839.11 ccw(c5392.7,2849.03) 5406.73,2849.03 ccw(c5420.75,2849.03) C193.2@5410.83,2839.11 ; U62.2@5403.65,929.5 cw(c5416.93,916.22) 5416.93,935 cw(c5416.93,953.78) U62.2@5403.65,940.5 ; C193.2@5406.72,2835 5406.73,2850.04 5415.06,2858.37 ; C332.2@5410.67,4790 5411.97,4790 5438.68,4816.71 5463.29,4816.71 v1(5465,4815) ; C332.2@5410.67,4795.81 ccw(c5410.67,4812.98) 5422.81,4800.84 ; C193.2@5411.88,2837.69 cw(c5427.57,2845.86) 5415.06,2858.37 ; C332.2@5416.48,4790 cw(c5427.37,4790) C332.2@5419.67,4797.7 ; v1(5440,1580) 5440,1625 5450.09,1635.09 U68.3@5477.39,1635.09 ; C98.2@5440.67,5430 5469.37,5430 5484.37,5445 C99.1@5484.37,5515 5580,5515 v1(5594.54,5529.73) ; C98.2@5444.78,5425.89 cw(c5454.7,5415.97) 5454.7,5430 cw(c5454.7,5444.03) C98.2@5444.78,5434.11 ; v1@5445.12,1364.88 U67.3@5477.6,1364.88 U67.3@5477.48,1365 ; 5447.6,4816.71 cw(c5447.6,4797.6) v1@5461.11,4811.11 ; C99.1@5474.69,5500.4 cw(c5451.33,5477.04) 5484.37,5477.04 cw(c5517.41,5477.04) C99.1@5494.05,5500.4 ; U68.3@5477.6,1634.88 U68.3@5477.39,1635.09 ; U68.3@5478.38,1635.09 U68.3@5477.39,1635.09 ; 5481.48,2842.09 ccw(c5493.22,2853.83) C257.2@5502.23,2839.88 ; 5483.68,2820.2 cw(c5505.38,2798.5) C257.2@5505.39,2829.19 ; C341.2@5489.74,1980.49 cw(c5458.44,1939.52) 5510,1939.52 ; 5491.98,2831.58 ccw(c5501.47,2841.07) C257.2@5508.74,2829.8 ; C99.1@5494.05,5505.32 cw(c5517.41,5481.96) 5517.41,5515 cw(c5517.41,5548.04) C99.1@5494.05,5524.68 ; v1@5494.64,1931.93 ccw(c5457.54,1969.02) C341.2@5510,1969.02 ; C341.2@5497.03,1990.03 cw(c5476.98,1963.79) 5510,1963.79 cw(c5543.02,1963.79) C341.2@5522.97,1990.03 ; v1(5498.52,1928.04) 5510,1939.52 ; C258.2@5501.28,2710.89 ccw(c5491.36,2700.97) 5491.36,2715 ccw(c5491.36,2729.03) C258.2@5501.28,2719.11 ; v1@5503.12,1923.44 ccw(c5486.51,1940.05) 5510,1940.05 ; C258.2@5505.39,2715 C192.2@5406.72,2715 5406.73,2791.71 5415.06,2800.04 5441.86,2800.04 5458.52,2816.71 5480.19,2816.71 ; C257.2@5505.39,2835 5493.52,2835 5493.52,2830.04 ; C341.2@5510,2007.01 5510,1939.52 ; C340.2@5510,2407.01 5541.97,2375.04 5573.52,2375.04 5587.19,2375.04 5603.74,2391.59 5605.93,2391.59 C337.2@5610,2395.67 5599.29,2406.37 v1(5572.52,2406.37) cw(c5572.53,2361.42) C337.2@5605.71,2391.75 ; C341.2@5530.26,1980.49 ccw(c5561.56,1939.52) 5510,1939.52 ; v1(5540.19,2218.04) 5545.86,2218.04 5547.19,2216.71 5573.96,2216.71 ; v1@5544.08,2221.93 ccw(c5556.69,2234.54) 5556.69,2216.71 ; v1@5576.41,2402.49 cw(c5585.8,2393.1) 5585.8,2406.37 cw(c5585.8,2419.65) v1@5576.41,2410.26 ; v1@5591.04,3619.02 ccw(c5599.93,3635.09) 5612.92,3622.1 ; 5594.19,3603.07 5594.19,3603.37 ; v1@5594.87,2612.6 cw(c5564.88,2578.89) C336.2@5610,2578.89 ; v1@5594.93,6073.89 ccw(c5585.54,6083.28) 5598.82,6083.28 ccw(c5612.1,6083.28) v1@5602.71,6073.89 ; v1@5594.93,6153.89 ccw(c5585.54,6163.28) 5598.82,6163.28 ccw(c5612.1,6163.28) v1@5602.71,6153.89 ; R119.2@5595.06,6110.75 cw(c5585.98,6101.67) 5598.82,6101.67 cw(c5611.66,6101.67) R119.2@5602.58,6110.75 ; R120.1@5595.06,6170.75 cw(c5585.98,6161.67) 5598.82,6161.67 cw(c5611.66,6161.67) R120.1@5602.58,6170.75 ; 5596.36,2384.21 cw(c5610,2370.56) C337.2@5610,2389.86 ; v1@5596.85,3629.52 ccw(c5607.96,3649.6) 5624.19,3633.37 ; v1@5598.52,2611.21 cw(c5598.52,2597.93) 5607.91,2607.32 cw(c5617.3,2616.71) v1@5604.02,2616.71 ; v1(5598.52,2616.71) 5610,2605.23 ; v1(5598.82,6070) R119.2@5598.82,6115 ; v1(5598.82,6150) R120.1@5598.82,6175 ; C337.2@5599.75,2406.37 cw(c5599.75,2386.3) C337.2@5614.57,2399.84 ; v1@5602.84,2621.56 cw(c5588.66,2605.62) 5610,2605.62 ; C339.2@5605.89,2004.78 ccw(c5595.97,2014.7) 5610,2014.7 ccw(c5624.03,2014.7) C339.2@5614.11,2004.78 ; C336.2@5605.89,2584.78 ccw(c5595.97,2594.7) 5610,2594.7 ccw(c5624.03,2594.7) C336.2@5614.11,2584.78 ; C336.2@5607.02,2586.1 cw(c5617.47,2567.05) 5632.82,2582.41 ; C339.2@5610,2000.67 5610,2024.04 5609,2025.04 5608.86,2025.04 ; C336.2@5610,2580.67 5610,2605.23 ; v4(5610,5470) 5679.21,5470 C256.2@5725.39,5516.18 ; 5610.44,2604.8 cw(c5593.23,2587.59) C336.2@5615.72,2578.31 ; v4@5614.11,5465.89 cw(c5624.03,5455.97) 5624.03,5470 cw(c5624.03,5484.03) v4@5614.11,5474.11 ; v1(5640.19,2764.37) 5625.86,2750.04 5581.86,2750.04 5573.52,2758.37 5540.19,2758.37 5481.02,2817.54 5480.19,2816.71 ; U63.2@5642.24,935 5680,935 5695,950 v1(5695,1045) ; 5642.6,2454 ccw(c5684.7,2496.1) C342.2@5701.59,2439.01 ; v1@5645.02,2066.71 cw(c5631.75,2066.71) 5641.14,2057.32 cw(c5650.52,2047.93) 5650.52,2061.21 cw(c5650.52,2047.93) 5659.91,2057.32 cw(c5669.3,2066.71) v1@5656.02,2066.71 ; v1@5652.66,2064.57 ccw(c5711.06,2122.97) C185.2@5711.06,2040.38 ; U63.2@5653.65,929.5 cw(c5666.93,916.22) 5666.93,935 cw(c5666.93,953.78) U63.2@5653.65,940.5 ; v1@5654.69,2062.54 cw(c5599.16,2007.01) C185.2@5677.69,2007.01 ; 5656.86,2439.73 ccw(c5691.21,2474.08) C342.2@5705,2427.5 ; 5669.28,2427.31 cw(c5648.98,2407.01) C342.2@5677.69,2407.01 ; 5671.13,2425.46 ccw(c5697.73,2452.06) C342.2@5708.4,2415.99 ; C185.2@5673.15,2044.08 ccw(c5711.06,2082) C185.2@5711.06,2028.38 ; C185.2@5675.18,2042.06 cw(c5640.13,2007.01) C185.2@5689.69,2007.01 ; v1(5682.52,3603.71) 5682.52,3616.04 5665.19,3633.37 5624.19,3633.37 ; v1(5683.03,1162.19) 5680.86,1164.37 5680.86,1180.04 ; v1@5686.82,1166.19 cw(c5699.94,1180.04) 5680.86,1180.04 ; 5690.02,1181.04 5681.86,1181.04 5680.86,1180.04 ; 5690.02,1181.35 5700.39,1191.71 C235.2@5700.39,1216.18 ; v4(5690,3351.71) v4@5690,3355 ; v1@5691.11,1041.11 cw(c5681.72,1031.72) 5695,1031.72 cw(c5708.28,1031.72) v1@5698.89,1041.11 ; v1@5692.64,1048.71 v1@5695,1046.35 ; C219.2@5696.01,1330.55 cw(c5722.94,1303.62) 5722.94,1341.71 ; C235.2@5696.28,1212.07 cw(c5686.36,1202.15) 5700.39,1202.15 cw(c5714.42,1202.15) C235.2@5704.5,1212.07 ; C219.2@5700.39,1326.18 5715.92,1341.71 v1(5756.86,1341.71) 5772.39,1326.18 C249.2@5840.39,1326.18 ; C219.2@5700.39,1331.99 ccw(c5700.39,1346.02) 5710.31,1336.1 ccw(c5720.23,1326.18) C219.2@5706.2,1326.18 ; C219.2@5704.5,1322.07 cw(c5751.91,1274.65) v1@5751.91,1341.71 ; C185.2@5715,2007.01 5710.22,2007.01 v1(5650.52,2066.71) 5608.86,2025.04 ; C342.2@5715,2407.01 5708.52,2407.01 5708.52,2408.37 5691.86,2425.04 5671.55,2425.04 5631.86,2464.74 5631.86,2583.37 5622.28,2592.95 5610,2605.23 ; C329.2@5719.55,3585.89 cw(c5709.96,3576.3) 5723.52,3576.3 ; C256.2@5719.58,5516.18 cw(c5705.55,5516.18) 5715.47,5506.26 cw(c5725.39,5496.34) C256.2@5725.39,5510.37 ; C255.2@5721.28,5622.07 cw(c5711.36,5612.15) 5725.39,5612.15 cw(c5739.42,5612.15) C255.2@5729.5,5622.07 ; 5723.52,3575.64 cw(c5738.02,3575.64) C329.2@5727.77,3585.89 ; C329.2@5723.66,3590 5723.52,3590 5723.52,3574.04 5772.52,3525.04 5829.19,3525.04 v1(5882.52,3578.37) ; C255.2@5725.39,5626.18 5725.39,5599.61 5730,5595 v4(5790,5595) ; R118.1@5735.06,6019.25 ccw(c5725.98,6028.33) 5738.82,6028.33 ccw(c5751.66,6028.33) R118.1@5742.58,6019.25 ; R118.1@5738.82,6015 5738.82,6057.67 v1@5739.52,6058.37 ; 5738.82,6039.37 cw(c5760.19,6039.37) v1@5745.08,6054.49 ; v1(5741.19,6058.37) v1@5739.52,6058.37 ; v1@5746.69,6058.37 cw(c5763.99,6058.37) 5751.76,6070.61 ; v1@5752.97,1337.82 ccw(c5743.58,1328.43) 5743.58,1341.71 ccw(c5743.58,1354.99) v1@5752.97,1345.6 ; 5763.41,6134.29 cw(c5783.31,6114.39) U20.2@5783.31,6142.54 ; 5768.63,6139.52 cw(c5778.12,6130.03) U20.2@5782.67,6142.65 ; 5772.26,6141.71 ccw(c5772.26,6155.46) U20.2@5781.98,6145.73 ; v4@5785.89,5590.89 ccw(c5775.97,5580.97) 5775.97,5595 ccw(c5775.97,5609.03) v4@5785.89,5599.11 ; U20.2@5792.17,6141.71 5770.82,6141.71 ; U20.2@5792.17,6144.41 5773.52,6144.41 5770.82,6141.71 ; v1(5795,5554.23) 5827.52,5554.04 5864.43,5554.04 ; v1@5798.87,5550.32 cw(c5808.2,5540.88) 5808.28,5554.16 cw(c5808.36,5567.43) v1@5798.91,5558.1 ; v1(5825.19,1633.37) 5857.24,1633.37 5882.24,1608.37 R160.2@5882.24,1590 ; v1@5829.08,1629.49 cw(c5838.47,1620.1) 5838.47,1633.37 cw(c5838.47,1646.65) v1@5829.08,1637.26 ; C250.2@5836.28,1212.07 cw(c5826.36,1202.15) 5840.39,1202.15 cw(c5854.42,1202.15) C250.2@5844.5,1212.07 ; C249.2@5836.28,1322.07 ccw(c5826.36,1312.15) 5826.36,1326.18 ccw(c5826.36,1340.21) C249.2@5836.28,1330.29 ; v1@5836.3,1128.93 ccw(c5826.91,1138.32) 5840.19,1138.32 ccw(c5853.47,1138.32) v1@5844.08,1128.93 ; v1(5840.19,1125.04) 5840.19,1183.18 5840.39,1183.37 C250.2@5840.39,1216.18 ; C226.2@5861.28,5520.29 ccw(c5851.36,5530.21) 5865.39,5530.21 ccw(c5879.42,5530.21) C226.2@5869.5,5520.29 ; C225.2@5861.28,5622.07 cw(c5851.36,5612.15) 5865.39,5612.15 cw(c5879.42,5612.15) C225.2@5869.5,5622.07 ; C226.2@5865.39,5516.18 C225.2@5865.39,5626.18 ; v1(5872.19,4797.04) 5891.67,4777.56 C293.2@5891.67,4770.41 ; v1@5877.02,3578.37 cw(c5863.75,3578.37) 5873.14,3568.99 cw(c5882.52,3559.6) v1@5882.52,3572.87 ; R160.2@5878.48,1594.25 ccw(c5869.39,1603.33) 5882.24,1603.33 ccw(c5895.08,1603.33) R160.2@5886,1594.25 ; v1@5882.52,3583.87 ccw(c5882.52,3597.15) 5891.91,3587.76 ccw(c5901.3,3578.37) v1@5888.02,3578.37 ; 5891.67,3587.52 5902.7,3598.56 5912.52,3608.37 5931.86,3608.37 5948.52,3625.04 ; U64.2@5892.24,935 5923.52,935 ; U64.2@5894.54,935 cw(c5894.54,887.72) v1@5927.97,921.15 ; U64.2@5903.65,929.5 cw(c5916.93,916.22) 5916.93,935 cw(c5916.93,953.78) U64.2@5903.65,940.5 ; R122.1@5912.42,6119.25 ccw(c5903.34,6128.33) 5916.18,6128.33 ccw(c5929.02,6128.33) R122.1@5919.94,6119.25 ; R121.1@5912.42,6170.75 cw(c5903.34,6161.67) 5916.18,6161.67 cw(c5929.02,6161.67) R121.1@5919.94,6170.75 ; R117.2@5916.18,6015 5964.23,6015 v1(5964.52,6014.71) ; R121.1@5916.18,6175 R122.1@5916.18,6115 5940.19,6115 v1(5945,6115) ; R117.2@5919.94,6011.24 cw(c5929.02,6002.16) 5929.02,6015 cw(c5929.02,6027.84) R117.2@5919.94,6018.76 ; R122.1@5919.94,6111.24 cw(c5929.02,6102.16) 5929.02,6115 cw(c5929.02,6127.84) R122.1@5919.94,6118.76 ; v1(5931.86,925.04) 5929.52,927.37 5929.52,929 5923.52,935 ; v1@5936.45,929.64 ccw(c5923.51,916.69) 5923.51,935 ; v1@5941.11,6111.11 ccw(c5931.72,6101.72) 5931.72,6115 ccw(c5931.72,6128.28) v1@5941.11,6118.89 ; 5950.54,6015 cw(c5950.54,6000.72) v1@5960.64,6010.82 ; 5951.95,6015 ccw(c5951.95,6027.28) v1@5960.64,6018.6 ; v1(5956.52,4479.04) 5980.96,4479.04 5990,4470 C319.2@5990,4446.89 ; v1@5960.41,4475.15 cw(c5969.8,4465.76) 5969.8,4479.04 cw(c5969.8,4492.32) v1@5960.41,4482.93 ; J30.GND2@5978.03,223.03 cw(c5937.06,182.06) 5995,182.06 cw(c6052.94,182.06) J30.GND2@6011.97,223.03 ; C321.2@5985.89,3810.89 cw(c5975.97,3800.97) 5990,3800.97 cw(c6004.03,3800.97) C321.2@5994.11,3810.89 ; C334.2@5985.89,4214.78 ccw(c5967.46,4233.21) v1@5993.52,4233.21 ; C319.2@5985.89,4451 ccw(c5975.97,4460.92) 5990,4460.92 ccw(c6004.03,4460.92) C319.2@5994.11,4451 ; v1(5987.19,4361.04) 5990.19,4364.04 v1@5990.19,4366.71 ; v1@5989.64,4235.82 cw(c5980.25,4226.43) 5993.52,4226.43 cw(c6006.8,4226.43) v1@5997.41,4235.82 ; C321.2@5990,3815 5990,3795 v1@6006.86,3778.14 ; C305.2@5990,3974.45 5990.19,3974.44 C305.2@5990.19,3974.71 ; C334.2@5990,4210.67 5993.52,4214.19 v1(5993.52,4239.71) ; v1@5991.11,172.38 ccw(c5981.72,181.77) 5995,181.77 ccw(c6008.28,181.77) v1@5998.89,172.38 ; J29.GND1@5991.12,2278.67 6043.86,2278.67 ; v1@5995,168.3 v1(5995,168.5) J30.GND2@5995,260 ; v1(6000,5540.19) 6000,5595 6015,5610 6070,5610 6113.31,5566.69 U60.1@6116.57,5566.69 ; v1@6004.5,3775 ccw(c5991.22,3775) 6000.61,3784.39 ccw(c6010,3793.78) v1@6010,3780.5 ; J29.GND1@6026.3,2266.25 cw(c6043.86,2260.05) 6043.86,2278.67 ; J29.GND1@6026.3,2291.09 ccw(c6043.86,2297.29) 6043.86,2278.67 ; 6043.86,2278.71 v1(6056.86,2291.71) ; 6115.9,4654.88 cw(c6143.96,4654.88) v1@6126.04,4676.48 ; 6131.86,4655.75 6130,4655.75 ; U14.34@6174.25,4655.75 6170,4655.75 6130,4655.75 ; 6181.9,4016.75 cw(c6215.19,3983.46) v1@6215.19,4030.54 ; v1@6186.52,3208.37 v1(6188.52,3206.37) ; 6191.52,4026.38 cw(c6205.83,4012.07) v1@6213.19,4030.92 ; U54.3@6198.29,6082.23 cw(c6188.37,6072.31) 6202.4,6072.31 cw(c6216.43,6072.31) U54.3@6206.51,6082.23 ; 6202.39,4037.24 cw(c6215.19,4024.43) v1@6215.19,4042.54 ; U54.3@6202.4,6100.12 6202.4,6057.6 6215.96,6044.04 v1(6256.52,6044.04) ; v1@6210.84,4039.41 cw(c6198.52,4048.96) 6198.52,4033.37 ; v1@6213.02,3809.04 ccw(c6199.75,3809.04) 6209.14,3818.43 ccw(c6218.52,3827.82) v1@6218.52,3814.54 ; v1(6215.19,4036.04) 6212.52,4033.37 6198.52,4033.37 ; v1(6218.52,3809.04) 6173.52,3854.04 6173.52,4008.37 6198.52,4033.37 ; C172.1@6221.56,6169.11 ccw(c6211.64,6179.03) 6225.67,6179.03 ccw(c6239.7,6179.03) 6229.78,6169.11 ccw(c6239.7,6179.03) 6239.7,6165 ; C172.1@6229.78,6160.89 cw(c6239.7,6150.97) 6239.7,6165 ; C172.1@6236.46,6165 ccw(c6236.46,6201.54) Y4.4@6262.3,6175.7 ; 6249.59,6165 cw(c6249.59,6139.68) Y4.4@6269.89,6154.82 ; v1@6252.64,6040.15 ccw(c6243.25,6030.76) 6243.25,6044.04 ccw(c6243.25,6057.32) v1@6252.64,6047.93 ; C168.2@6255.22,6210.89 ccw(c6245.3,6200.97) 6245.3,6215 ccw(c6245.3,6229.03) C168.2@6255.22,6219.11 ; C168.2@6259.33,6215 6240.67,6215 6225.67,6200 C172.1@6225.67,6165 ; Y4.4@6260.27,6147.65 ccw(c6225.67,6121.84) C172.1@6225.67,6165 ; v1@6260.3,6087.26 ccw(c6250.91,6096.65) 6264.19,6096.65 ccw(c6277.47,6096.65) v1@6268.08,6087.26 ; v1(6264.19,6083.37) 6264.19,6101.69 6277.5,6115 ; Y4.4@6264.19,6165 C172.1@6225.67,6165 ; Y4.4@6266.64,6133.95 cw(c6255.55,6115) 6277.5,6115 ; Y4.4@6277.5,6156.5 6277.5,6115 ; Y4.4@6288.36,6133.95 ccw(c6299.45,6115) 6277.5,6115 ; J29.6@6292.99,1366.37 cw(c6264.25,1337.63) 6304.9,1337.63 cw(c6345.54,1337.63) J29.6@6316.8,1366.37 ; J29.6@6304.9,1404.65 6304.9,1324.71 6331.56,1298.04 6537.19,1298.04 v1(6578.52,1339.37) 6578.52,1395.2 J29.3@6569.07,1404.65 ; Y4.2@6358.31,6013.65 ccw(c6330.79,6045) 6372.5,6045 ccw(c6414.22,6045) Y4.2@6386.69,6013.65 ; v1@6368.61,6041.3 cw(c6359.22,6031.92) 6372.5,6031.92 cw(c6385.78,6031.92) v1@6376.39,6041.3 ; Y4.2@6372.5,5993.5 v1@6372.5,6045 ; v1(6440.19,1008.37) 6458.37,1008.37 6518.78,1068.78 ; v1@6444.08,1004.49 cw(c6453.47,995.1) 6453.47,1008.37 cw(c6453.47,1021.65) v1@6444.08,1012.26 ; C174.1@6496.56,5910.89 cw(c6486.64,5900.97) 6500.67,5900.97 cw(c6514.7,5900.97) C174.1@6504.78,5910.89 ; v1@6496.78,5880.41 ccw(c6487.39,5889.8) 6500.67,5889.8 ccw(c6513.95,5889.8) v1@6504.56,5880.41 ; v1(6500.67,5876.52) C174.1@6500.67,5915 ; J30.3@6508.83,1088.39 cw(c6494.48,1068.78) 6518.78,1068.78 ; J30.3@6518.78,1128.35 6518.78,1068.78 ; J30.3@6528.72,1088.39 ccw(c6543.08,1068.78) 6518.78,1068.78 ; v1(6532.52,2245.37) 6548.86,2261.71 6612.52,2261.71 v2@6614.52,2259.71 ; v1@6532.52,2250.87 ccw(c6532.52,2264.15) 6541.91,2254.76 ccw(c6551.3,2245.37) v1@6538.02,2245.37 ; v1@6550.64,4646.15 cw(c6541.25,4636.76) 6554.52,4636.76 cw(c6567.8,4636.76) v1@6558.41,4646.15 ; v1(6554.52,4650.04) 6554.52,4630.48 6560.75,4624.25 6571.86,4624.25 ; J29.3@6562.38,1362.83 cw(c6551.74,1338.24) v1@6578.52,1338.24 ; J29.3@6567.15,1373.84 cw(c6559.65,1356.52) J29.3@6578.52,1356.52 ; 6571.86,4624.37 6571.86,4624.25 ; v1@6573.02,1339.37 cw(c6559.75,1339.37) 6569.14,1329.99 cw(c6578.52,1320.6) v1@6578.52,1333.87 ; v1@6574.64,1343.26 ccw(c6565.25,1352.65) 6578.52,1352.65 ccw(c6591.8,1352.65) v1@6582.41,1343.26 ; 6592.14,2261.71 cw(c6592.14,2234.54) v2@6611.35,2253.75 ; C173.1@6655.22,5910.89 cw(c6645.3,5900.97) 6659.33,5900.97 cw(c6673.36,5900.97) C173.1@6663.44,5910.89 ; U55.2@6657.24,6425 6681.86,6425 ; C173.1@6659.33,5915 6659.33,5815.67 6675,5800 v1(6705,5800) ; U55.2@6660.73,6421.55 ccw(c6669.4,6433.91) 6680.09,6423.23 ; U55.2@6667.62,6431.37 ccw(c6677.73,6445.79) 6690.19,6433.33 ; U55.2@6668.67,6419.51 cw(c6681.86,6406.4) 6681.86,6425 ; U55.2@6668.67,6430.49 ccw(c6681.86,6443.6) 6681.86,6425 ; v1@6672.93,4737.11 ccw(c6688.48,4752.67) 6688.48,4730.67 ; 6675.08,4624.25 cw(c6675.08,4596.6) v1@6694.64,4616.15 ; v1(6677.52,4741.71) 6677.52,4733.33 6680.19,4730.67 C77.2@6735,4730.67 6798.29,4667.37 6798.52,4667.37 6798.52,4658.08 6800.86,4655.75 U15.34@6845.59,4655.75 6885.19,4655.75 6887.52,4658.08 6887.52,4658.37 v1(6890.19,4658.37) ; v1@6681.41,4745.6 ccw(c6717.45,4781.64) 6717.45,4730.67 ; v1@6686.11,6496.11 cw(c6676.26,6486.26) 6690.19,6486.26 ; 6690.19,6487.18 cw(c6702.82,6487.18) v1@6693.89,6496.11 ; v1@6690.99,6500 6690.19,6499.2 6690.19,6433.33 ; J10.5@6690.99,6579.01 6695,6575 v1(6725,6575) ; v1(6698.52,4620.04) 6694.31,4624.25 U14.12@6619.41,4624.25 6571.86,4624.25 ; v1@6701.11,5796.11 ccw(c6691.72,5786.72) 6691.72,5800 ccw(c6691.72,5813.28) v1@6701.11,5803.89 ; v1@6721.11,6571.11 ccw(c6711.72,6561.72) 6711.72,6575 ccw(c6711.72,6588.28) v1@6721.11,6578.89 ; v5@6730.17,6043.59 cw(c6714.83,6028.25) 6736.52,6028.25 ; C71.2@6730.89,4403.81 cw(c6720.97,4393.89) 6735,4393.89 cw(c6749.03,4393.89) C71.2@6739.11,4403.81 ; C75.2@6730.89,4594.07 ccw(c6720.97,4603.99) 6735,4603.99 ccw(c6749.03,4603.99) C75.2@6739.11,4594.07 ; C77.2@6730.89,4726.56 ccw(c6720.97,4716.64) 6720.97,4730.67 ccw(c6720.97,4744.7) C77.2@6730.89,4734.78 ; v1(6731.86,1124.37) 6771.98,1124.37 J30.6@6775.95,1128.35 ; v1(6731.86,2370.71) 6754.29,2370.71 NT5.2@6770,2355 ; v1@6732.72,1124.37 ccw(c6732.72,1178.58) J30.6@6771.05,1140.25 ; v5@6733.52,6044.37 6736.52,6041.37 6736.52,6020.37 6740,6012 U56.28@6748.52,6008.37 ; C71.2@6735,4407.92 6735,4383.37 6735.19,4383.37 6748.52,4370.04 v1(6748.52,4335.04) ; C75.2@6735,4589.96 6735,4605 6745.04,4615.04 v1(6767.19,4615.04) ; C77.2@6735,4724.86 cw(c6735,4710.83) 6744.92,4720.75 cw(c6754.84,4730.67) C77.2@6740.81,4730.67 ; C73.2@6735,4830.04 6735,4825.93 6768.19,4792.74 v1(6768.19,4789.37) ; v1@6735.75,1120.49 cw(c6745.14,1111.1) 6745.14,1124.37 cw(c6745.14,1137.65) v1@6735.75,1128.26 ; v1@6735.75,2366.82 cw(c6745.14,2357.43) 6745.14,2370.71 cw(c6745.14,2383.99) v1@6735.75,2374.6 ; v1@6744.64,4338.93 ccw(c6735.25,4348.32) 6748.52,4348.32 ccw(c6761.8,4348.32) v1@6752.41,4338.93 ; 6751.9,1124.37 cw(c6751.9,1097.29) J30.6@6771.05,1116.44 ; 6756.42,4804.51 cw(c6741.29,4789.37) v1@6762.69,4789.37 ; 6762.32,2362.68 ccw(c6770,2370.36) NT5.2@6770,2359.5 ; v1@6763.3,4611.15 ccw(c6753.91,4601.76) 6753.91,4615.04 ccw(c6753.91,4628.32) v1@6763.3,4618.93 ; U56.28@6764.33,6007.05 6764.65,6006.73 6788.31,6006.73 6795,6000.04 ; NT7.2@6800,2355 6820,2375 v1(6845,2375) v1@6845.26,2374.74 ; NT7.2@6800,2359.5 ccw(c6800,2370.36) 6807.68,2362.68 ; v1@6841.11,2371.11 ccw(c6831.72,2361.72) 6831.72,2375 ccw(c6831.72,2388.28) v1@6841.11,2378.89 ; U15.34@6870.57,4655.75 ccw(c6870.57,4678) v1@6886.3,4662.26 ; R246.2@7058.44,5858.3 ccw(c7057.29,5874.14) R246.2@7069.3,5863.75 ; R246.2@7060.1,5853.11 C170.1@7100.67,5900 ; J30.GND1@7074.19,282.14 ccw(c7019.76,336.57) v1@7096.73,336.57 ; J30.GND1@7082.67,273.66 ccw(c7048.73,307.6) J30.GND1@7096.73,307.6 ; v1@7092.84,335.69 cw(c7083.45,326.3) 7096.73,326.3 cw(c7110.01,326.3) v1@7100.62,335.69 ; J29.GND2@7093.48,2278.67 7093.48,2313.48 v1(7125,2345) ; C170.1@7094.87,5899.58 cw(c7080.88,5898.57) 7091.49,5889.39 cw(c7102.1,5880.21) C170.1@7101.09,5894.2 ; J30.GND1@7096.46,254.06 J30.GND1@7096.73,254.33 v1(7096.73,339.58) ; J30.GND1@7096.73,306.29 ccw(c7142.89,306.29) J30.GND1@7110.25,273.66 ; v1@7096.73,335.26 ccw(c7171.86,335.26) J30.GND1@7118.73,282.14 ; J29.GND2@7104.1,2286.23 cw(c7127.29,2305.06) 7106.17,2326.17 ; J29.GND2@7113.42,2293.8 cw(c7137.68,2313.49) 7115.59,2335.59 ; v1@7119.5,2345 cw(c7106.22,2345) 7115.61,2335.61 cw(c7125,2326.22) v1@7125,2339.5 ; J29.GND2@7122.74,2301.36 cw(c7148.07,2321.92) v1(7125,2345) ; C171.2@7146.98,5969.56 cw(c7141.55,5954.04) v1@7157.99,5954.04 ; C171.2@7157.99,5963.13 ccw(c7178.13,5963.13) v1@7163.89,5948.89 ; C171.2@7157.99,6005 v1@7157.99,5954.04 ; C171.2@7169.01,5969.56 ccw(c7174.43,5954.04) v1@7157.99,5954.04 ; v1(7198.52,2941.71) 7425.86,2941.71 v1(7459.19,2975.04) ; v1@7202.41,2937.82 cw(c7211.8,2928.43) 7211.8,2941.71 cw(c7211.8,2954.99) v1@7202.41,2945.6 ; v1@7240.3,554.49 cw(c7230.91,545.1) 7244.19,545.1 cw(c7257.47,545.1) v1@7248.08,554.49 ; v1@7240.3,562.26 ccw(c7230.91,571.65) 7244.19,571.65 ccw(c7257.47,571.65) v1@7248.08,562.26 ; 7244.19,541.44 ccw(c7275.77,541.44) C94.2@7253.44,519.11 ; C94.2@7249.33,509.19 cw(c7249.33,495.16) 7259.25,505.08 cw(c7269.17,515) C94.2@7255.14,515 ; v1@7250.97,1327.26 ccw(c7241.23,1337) 7255,1337 ; v1(7254.86,1323.37) 7255,1323.52 NT4.2@7255,1350 ; v1(7255,320) J9.5@7304.02,320 ; 7255,1336.31 ccw(c7267.79,1336.31) v1@7258.75,1327.26 ; v1@7258.89,316.11 cw(c7268.28,306.72) 7268.28,320 cw(c7268.28,333.28) v1@7258.89,323.89 ; U19.14@7292.05,595.67 7260.67,595.67 7244.19,579.19 v1(7244.19,558.37) 7244.19,520.14 C94.2@7249.33,515 7271.14,493.19 7350.94,493.19 U18.2@7352.76,495 ; U15.12@7294.41,4624.25 7347.86,4624.25 7348.52,4624.92 7348.52,4625.04 ; C91.1@7311.56,994.11 ccw(c7301.64,1004.03) 7315.67,1004.03 ccw(c7329.7,1004.03) C91.1@7319.78,994.11 ; C91.1@7315.67,990 7315.67,1015.67 7322.37,1022.37 7365.19,1022.37 ; 7323.7,493.19 ccw(c7323.7,518.15) U18.2@7341.35,500.5 ; 7332.44,493.19 cw(c7332.44,480.59) U18.2@7341.35,489.5 ; v1@7342.64,4639.49 cw(c7328.42,4625.27) 7348.52,4625.27 ; v1(7346.52,4643.37) 7348.52,4641.37 7348.52,4625.04 ; 7366.17,4621.4 cw(c7334.73,4589.96) C74.2@7379.19,4589.96 ; C92.1@7375.22,994.11 ccw(c7365.3,1004.03) 7379.33,1004.03 ccw(c7393.36,1004.03) C92.1@7383.44,994.11 ; C92.1@7379.33,990 7379.33,1019.66 7376.62,1022.37 7365.19,1022.37 ; C76.2@7380.89,4403.81 cw(c7370.97,4393.89) 7385,4393.89 cw(c7399.03,4393.89) C76.2@7389.11,4403.81 ; C72.2@7380.89,4734.78 ccw(c7370.97,4744.7) 7385,4744.7 ccw(c7399.03,4744.7) C72.2@7389.11,4734.78 ; C78.2@7380.89,4875.49 ccw(c7370.97,4885.41) 7385,4885.41 ccw(c7399.03,4885.4) C78.2@7389.11,4875.49 ; 7381.86,1039.04 7365.19,1022.37 ; C76.2@7385,4407.92 7385,4391.71 7393.33,4383.37 7398.52,4383.37 7418.19,4363.71 v1(7418.19,4359.04) ; C74.2@7385,4589.96 7385,4602.37 7385.19,4602.37 ; C72.2@7385,4730.67 7385,4763.18 v1(7396.86,4775.04) 7456.86,4775.04 7473.52,4791.71 7473.52,4840.71 7469.52,4836.71 v1(7469.52,4836.6) ; C72.2@7385,4733.14 cw(c7438.76,4733.14) 7400.75,4771.15 cw(c7410.14,4761.76) 7410.14,4775.04 cw(c7410.14,4788.32) v1@7400.75,4778.93 ; 7385,4762.11 cw(c7409.79,4762.11) v1@7392.26,4779.64 ; C78.2@7385,4871.38 7385,4895.52 v1(7417.19,4927.71) ; C74.2@7390.81,4589.96 cw(c7434.35,4589.96) 7403.56,4620.75 ; 7405.5,4376.4 cw(c7388.15,4359.04) v1@7412.69,4359.04 ; v1@7411.69,4927.71 cw(c7398.41,4927.71) 7407.8,4918.32 cw(c7417.19,4908.93) v1@7417.19,4922.21 ; v1@7429.97,4672.15 cw(c7420.58,4662.76) 7433.86,4662.76 cw(c7447.14,4662.76) v1@7437.75,4672.15 ; v1(7431.86,1308.37) 7452.86,1329.37 7452.99,1329.37 C93.2@7452.99,1374 v1@7522.19,1374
